// Mitsubishi GX Works2 project: 42.6个灯循环点亮隔1秒（位移指令）   PLC: FX3U/FX3UC

PROGRAM MAIN
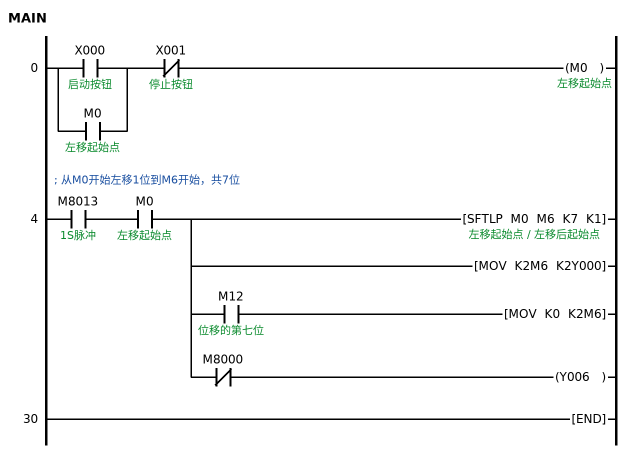
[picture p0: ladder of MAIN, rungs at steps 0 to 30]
0     LD      X000  ; 启动按钮
      OR      M0  ; 左移起始点
      ANI     X001  ; 停止按钮
      OUT     M0  ; 左移起始点
; 从M0开始左移1位到M6开始，共7位
4     LD      M8013  ; 1S脉冲
      AND     M0  ; 左移起始点
      SFTLP   M0 M6 K7 K1  ; 左移后起始点
        [note] K7:多1位用来关闭所有灯.
      MOV     K2M6 K2Y000
      MPS
      AND     M12  ; 位移的第七位
      MOV     K0 K2M6
        [note] 到M12关闭所有灯
      MPP
      ANI     M8000
      OUT     Y006
        [note] Y6永远不亮
30    END
END_PROGRAM
